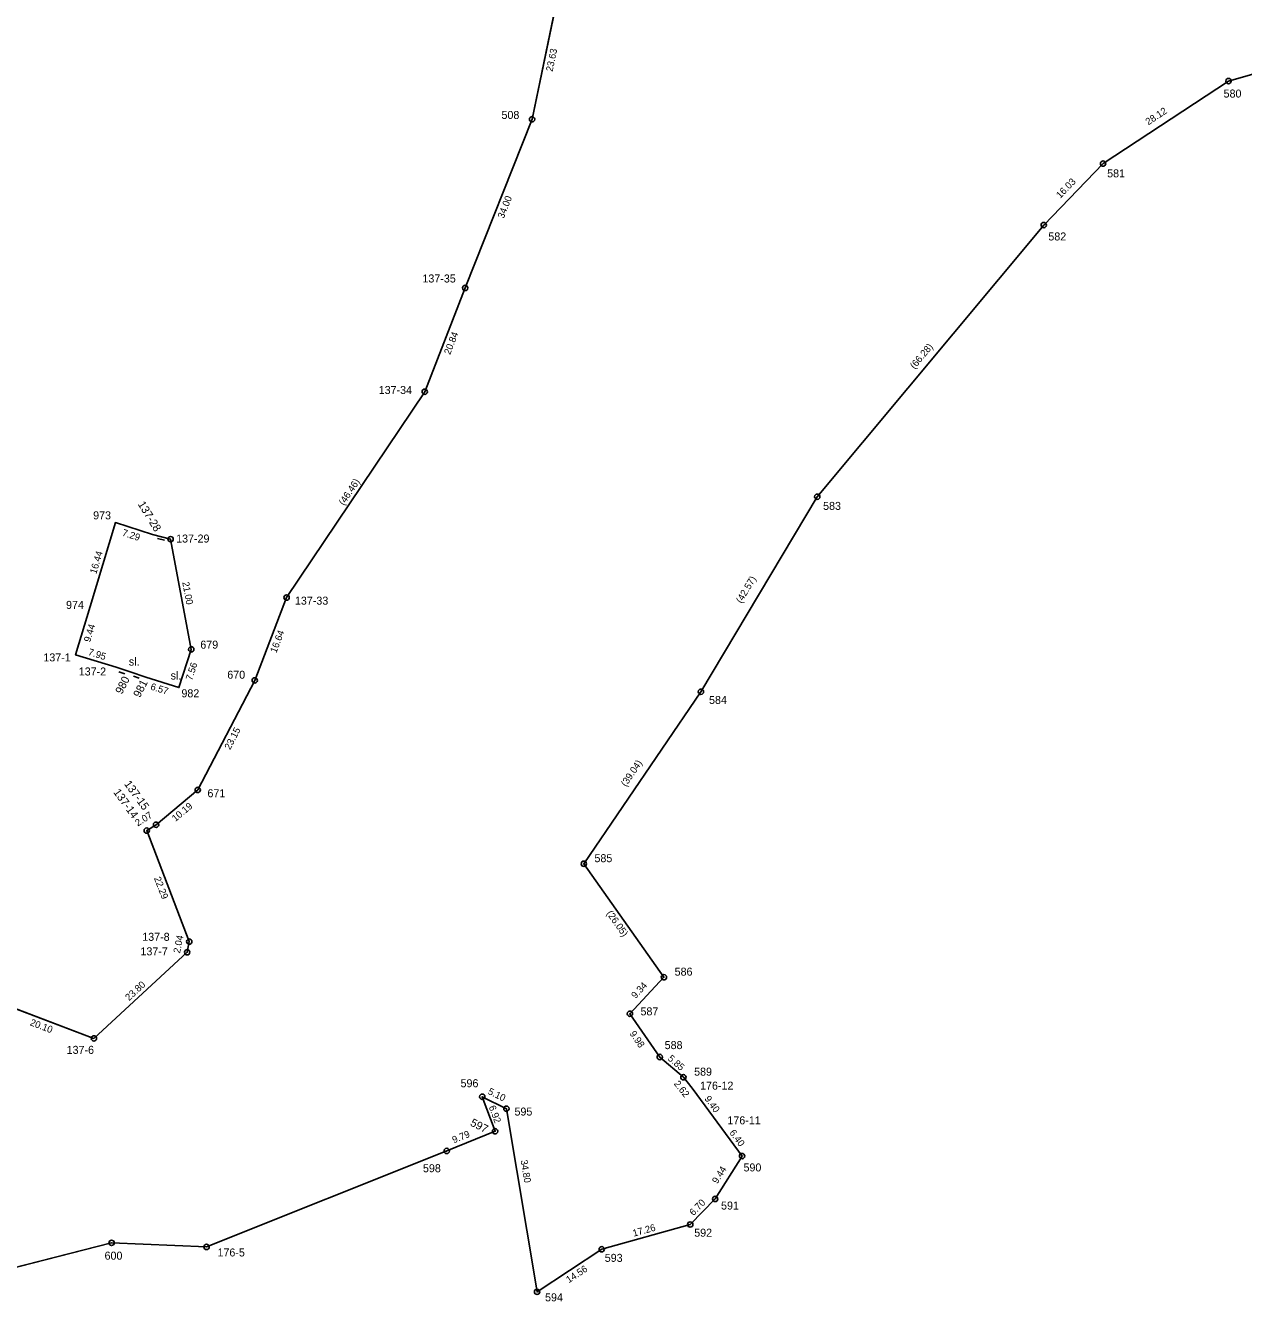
# Model space of a CAD drawing. Extents: x -555170 to -550532, y -1039598 to -1034701.
# Drawn here: x -554719.5 to -554491.3, y -1038084.3 to -1037842.9 of the extents above; entities that cross this region are included whole.
import ezdxf

# ---------------------------------------------------------------- set-up
doc = ezdxf.new("R2010")
doc.units = 0
for name, color, linetype in [('Vrstva 10', 7, 'Continuous'), ('Vrstva 40', 7, 'Continuous'), ('Vrstva 43', 7, 'Continuous'), ('Vrstva 48', 7, 'Continuous')]:
    doc.layers.add(name, color=color, linetype=linetype)

msp = doc.modelspace()

# ---------------------------------------------------------------- linework, layer by layer
at = {"layer": 'Vrstva 10'}
for p, q in [((-554693.54, -1037939.36), (-554694.82, -1037939.07)), ((-554701, -1037964.39), (-554702.12, -1037964.05)), ((-554698.29, -1037965.2), (-554699.35, -1037964.84))]:
    msp.add_line(p, q, dxfattribs=at)
at = {"layer": 'Vrstva 40'}
for p, q in [((-554619.81, -1037837.33), (-554624.63, -1037860.46)), ((-554494.07, -1037853.28), (-554482.94, -1037850.1)), ((-554517.59, -1037868.76), (-554494.07, -1037853.28)), ((-554624.63, -1037860.46), (-554637.17, -1037892.08)), ((-554528.71, -1037880.28), (-554517.59, -1037868.76)), ((-554571.15, -1037931.2), (-554528.71, -1037880.28)), ((-554637.17, -1037892.08), (-554644.76, -1037911.53)), ((-554644.76, -1037911.53), (-554670.64, -1037950.11)), ((-554592.96, -1037967.76), (-554571.15, -1037931.2)), ((-554702.73, -1037936.06), (-554707.46, -1037951.79)), ((-554695.8, -1037938.3), (-554702.73, -1037936.06)), ((-554692.38, -1037939.17), (-554695.8, -1037938.3)), ((-554688.52, -1037959.82), (-554692.38, -1037939.17)), ((-554670.64, -1037950.11), (-554676.61, -1037965.64)), ((-554707.46, -1037951.79), (-554710.2, -1037960.85)), ((-554710.2, -1037960.85), (-554702.61, -1037963.19)), ((-554690.82, -1037967), (-554688.52, -1037959.82)), ((-554702.61, -1037963.19), (-554699.98, -1037964.06)), ((-554699.98, -1037964.06), (-554697.06, -1037965.04)), ((-554697.06, -1037965.04), (-554690.82, -1037967)), ((-554676.61, -1037965.64), (-554687.3, -1037986.17)), ((-554614.93, -1038000.02), (-554592.96, -1037967.76)), ((-554687.3, -1037986.17), (-554695.12, -1037992.69)), ((-554695.12, -1037992.69), (-554696.87, -1037993.79)), ((-554696.87, -1037993.79), (-554688.89, -1038014.6)), ((-554599.9, -1038021.29), (-554614.93, -1038000.02)), ((-554689.29, -1038016.61), (-554706.76, -1038032.76)), ((-554688.89, -1038014.6), (-554689.29, -1038016.61)), ((-554606.27, -1038028.12), (-554599.9, -1038021.29)), ((-554706.76, -1038032.76), (-554725.56, -1038025.63)), ((-554600.69, -1038036.24), (-554606.27, -1038028.12)), ((-554596.25, -1038040.04), (-554600.69, -1038036.24)), ((-554594.63, -1038042.1), (-554596.25, -1038040.04)), ((-554589.08, -1038049.67), (-554594.63, -1038042.1)), ((-554631.56, -1038050.17), (-554633.97, -1038043.68)), ((-554633.97, -1038043.68), (-554629.43, -1038045.93)), ((-554629.43, -1038045.93), (-554623.69, -1038080.26)), ((-554640.63, -1038053.86), (-554631.56, -1038050.17)), ((-554585.27, -1038054.81), (-554589.08, -1038049.67)), ((-554685.65, -1038071.84), (-554640.63, -1038053.86)), ((-554590.31, -1038062.84), (-554585.27, -1038054.81)), ((-554594.98, -1038067.64), (-554590.31, -1038062.84)), ((-554611.56, -1038072.28), (-554594.98, -1038067.64)), ((-554754.97, -1038084.28), (-554703.45, -1038071.08)), ((-554703.45, -1038071.08), (-554685.65, -1038071.84)), ((-554623.69, -1038080.26), (-554611.56, -1038072.28))]:
    msp.add_line(p, q, dxfattribs=at)
at = {"layer": 'Vrstva 43'}
for p, q in [((-554494.07, -1037853.28), (-554494.07, -1037853.28)), ((-554624.63, -1037860.46), (-554624.63, -1037860.46)), ((-554517.59, -1037868.76), (-554517.59, -1037868.76)), ((-554528.71, -1037880.28), (-554528.71, -1037880.28)), ((-554637.17, -1037892.08), (-554637.17, -1037892.08)), ((-554644.76, -1037911.53), (-554644.76, -1037911.53)), ((-554571.15, -1037931.2), (-554571.15, -1037931.2)), ((-554702.73, -1037936.06), (-554702.73, -1037936.06)), ((-554695.8, -1037938.3), (-554695.8, -1037938.3)), ((-554692.38, -1037939.17), (-554692.38, -1037939.17)), ((-554670.64, -1037950.11), (-554670.64, -1037950.11)), ((-554707.46, -1037951.79), (-554707.46, -1037951.79)), ((-554710.2, -1037960.85), (-554710.2, -1037960.85)), ((-554688.52, -1037959.82), (-554688.52, -1037959.82)), ((-554702.61, -1037963.19), (-554702.61, -1037963.19)), ((-554699.98, -1037964.06), (-554699.98, -1037964.06)), ((-554697.06, -1037965.04), (-554697.06, -1037965.04)), ((-554676.61, -1037965.64), (-554676.61, -1037965.64)), ((-554690.82, -1037967), (-554690.82, -1037967)), ((-554592.96, -1037967.76), (-554592.96, -1037967.76)), ((-554687.3, -1037986.17), (-554687.3, -1037986.17)), ((-554696.87, -1037993.79), (-554696.87, -1037993.79)), ((-554695.12, -1037992.69), (-554695.12, -1037992.69)), ((-554614.93, -1038000.02), (-554614.93, -1038000.02)), ((-554689.29, -1038016.61), (-554689.29, -1038016.61)), ((-554688.89, -1038014.6), (-554688.89, -1038014.6)), ((-554599.9, -1038021.29), (-554599.9, -1038021.29)), ((-554606.27, -1038028.12), (-554606.27, -1038028.12)), ((-554706.76, -1038032.76), (-554706.76, -1038032.76)), ((-554600.69, -1038036.24), (-554600.69, -1038036.24)), ((-554596.25, -1038040.04), (-554596.25, -1038040.04)), ((-554594.63, -1038042.1), (-554594.63, -1038042.1)), ((-554633.97, -1038043.68), (-554633.97, -1038043.68)), ((-554629.43, -1038045.93), (-554629.43, -1038045.93)), ((-554631.56, -1038050.17), (-554631.56, -1038050.17)), ((-554589.08, -1038049.67), (-554589.08, -1038049.67)), ((-554640.63, -1038053.86), (-554640.63, -1038053.86)), ((-554585.27, -1038054.81), (-554585.27, -1038054.81)), ((-554590.31, -1038062.84), (-554590.31, -1038062.84)), ((-554594.98, -1038067.64), (-554594.98, -1038067.64)), ((-554703.45, -1038071.08), (-554703.45, -1038071.08)), ((-554685.65, -1038071.84), (-554685.65, -1038071.84)), ((-554611.56, -1038072.28), (-554611.56, -1038072.28)), ((-554623.69, -1038080.26), (-554623.69, -1038080.26))]:
    msp.add_line(p, q, dxfattribs=at)
for centre, radius in [((-554494.07, -1037853.28), 0.5), ((-554494.07, -1037853.28), 0.01), ((-554624.63, -1037860.46), 0.5), ((-554624.63, -1037860.46), 0.01), ((-554517.59, -1037868.76), 0.5), ((-554517.59, -1037868.76), 0.01), ((-554528.71, -1037880.28), 0.5), ((-554528.71, -1037880.28), 0.01), ((-554637.17, -1037892.08), 0.5), ((-554637.17, -1037892.08), 0.01), ((-554644.76, -1037911.53), 0.5), ((-554644.76, -1037911.53), 0.01), ((-554571.15, -1037931.2), 0.5), ((-554571.15, -1037931.2), 0.01), ((-554692.38, -1037939.17), 0.5), ((-554692.38, -1037939.17), 0.01), ((-554670.64, -1037950.11), 0.5), ((-554670.64, -1037950.11), 0.01), ((-554688.52, -1037959.82), 0.5), ((-554688.52, -1037959.82), 0.01), ((-554676.61, -1037965.64), 0.5), ((-554676.61, -1037965.64), 0.01), ((-554592.96, -1037967.76), 0.5), ((-554592.96, -1037967.76), 0.01), ((-554687.3, -1037986.17), 0.5), ((-554687.3, -1037986.17), 0.01), ((-554695.12, -1037992.69), 0.5), ((-554696.87, -1037993.79), 0.5), ((-554696.87, -1037993.79), 0.01), ((-554695.12, -1037992.69), 0.01), ((-554614.93, -1038000.02), 0.5), ((-554614.93, -1038000.02), 0.01), ((-554688.89, -1038014.6), 0.5), ((-554689.29, -1038016.61), 0.5), ((-554689.29, -1038016.61), 0.01), ((-554688.89, -1038014.6), 0.01), ((-554599.9, -1038021.29), 0.5), ((-554599.9, -1038021.29), 0.01), ((-554606.27, -1038028.12), 0.5), ((-554606.27, -1038028.12), 0.01), ((-554706.76, -1038032.76), 0.5), ((-554706.76, -1038032.76), 0.01), ((-554600.69, -1038036.24), 0.5), ((-554600.69, -1038036.24), 0.01), ((-554596.25, -1038040.04), 0.5), ((-554596.25, -1038040.04), 0.01), ((-554633.97, -1038043.68), 0.5), ((-554633.97, -1038043.68), 0.01), ((-554629.43, -1038045.93), 0.5), ((-554629.43, -1038045.93), 0.01), ((-554631.56, -1038050.17), 0.5), ((-554631.56, -1038050.17), 0.01), ((-554640.63, -1038053.86), 0.5), ((-554640.63, -1038053.86), 0.01), ((-554585.27, -1038054.81), 0.5), ((-554585.27, -1038054.81), 0.01), ((-554590.31, -1038062.84), 0.5), ((-554590.31, -1038062.84), 0.01), ((-554594.98, -1038067.64), 0.5), ((-554594.98, -1038067.64), 0.01), ((-554703.45, -1038071.08), 0.5), ((-554703.45, -1038071.08), 0.01), ((-554685.65, -1038071.84), 0.5), ((-554685.65, -1038071.84), 0.01), ((-554611.56, -1038072.28), 0.5), ((-554611.56, -1038072.28), 0.01), ((-554623.69, -1038080.26), 0.5), ((-554623.69, -1038080.26), 0.01)]:
    msp.add_circle(centre, radius, dxfattribs=at)
at = {"layer": 'Vrstva 48'}
for points in [[(-554725.56, -1038025.63), (-554706.76, -1038032.76), (-554689.29, -1038016.61), (-554688.89, -1038014.6), (-554696.87, -1037993.79), (-554695.12, -1037992.69), (-554687.3, -1037986.17), (-554676.61, -1037965.64), (-554670.64, -1037950.11), (-554644.76, -1037911.53), (-554637.17, -1037892.08), (-554624.63, -1037860.46), (-554619.81, -1037837.33)], [(-554482.94, -1037850.1), (-554494.07, -1037853.28), (-554517.59, -1037868.76), (-554528.71, -1037880.28), (-554571.15, -1037931.2), (-554592.96, -1037967.76), (-554614.93, -1038000.02), (-554599.9, -1038021.29), (-554606.27, -1038028.12), (-554600.69, -1038036.24), (-554596.25, -1038040.04), (-554594.63, -1038042.1), (-554589.08, -1038049.67), (-554585.27, -1038054.81), (-554590.31, -1038062.84), (-554594.98, -1038067.64), (-554611.56, -1038072.28), (-554623.69, -1038080.26), (-554629.43, -1038045.93), (-554633.97, -1038043.68), (-554631.56, -1038050.17), (-554640.63, -1038053.86), (-554685.65, -1038071.84), (-554703.45, -1038071.08), (-554754.97, -1038084.28)], [(-554702.61, -1037963.19), (-554710.2, -1037960.85), (-554707.46, -1037951.79), (-554702.73, -1037936.06), (-554695.8, -1037938.3), (-554692.38, -1037939.17), (-554688.52, -1037959.82), (-554690.82, -1037967), (-554697.06, -1037965.04), (-554699.98, -1037964.06), (-554702.61, -1037963.19)]]:
    msp.add_lwpolyline(points, dxfattribs=at)

# ---------------------------------------------------------------- texts
at = {"layer": 'Vrstva 10'}
for s, rotation, p in [('23.63', 78.2168, (-554620.79, -1037851.6)), ('28.12', 33.3514, (-554509.1, -1037861.6)), ('16.03', 46.0122, (-554525.61, -1037875.38)), ('34.00', 68.3742, (-554629.95, -1037879.16)), ('20.84', 68.6827, (-554639.99, -1037904.67)), ('(66.28)', 50.1933, (-554552.91, -1037907.37)), ('(46.46)', 56.1457, (-554659.91, -1037932.94)), ('7.29', 342.0875, (-554701.58, -1037938.48)), ('16.44', 73.264, (-554706.33, -1037945.79)), ('(42.57)', 59.1798, (-554585.37, -1037951.3)), ('21.00', 280.5922, (-554690.21, -1037947.26)), ('9.44', 73.1732, (-554707.47, -1037958.56)), ('16.64', 68.9713, (-554672.58, -1037960.6)), ('7.95', 342.8655, (-554707.96, -1037960.86)), ('7.56', 72.2436, (-554688.37, -1037965.75)), ('6.57', 342.5624, (-554696.27, -1037967.33)), ('23.15', 62.4958, (-554681.23, -1037978.74)), ('(39.04)', 55.7362, (-554607.01, -1037985.66)), ('10.19', 39.8168, (-554691.49, -1037992.2)), ('2.07', 32.1523, (-554698.54, -1037993.05)), ('22.29', 290.9803, (-554695.53, -1038002.72)), ('(26.05)', 305.2609, (-554610.75, -1038009.32)), ('2.04', 78.7449, (-554690.63, -1038016.87)), ('23.80', 42.7516, (-554700.18, -1038025.79)), ('9.34', 46.9658, (-554605.24, -1038025.4)), ('20.10', 339.2385, (-554718.86, -1038030.26)), ('9.98', 304.5258, (-554606.4, -1038031.87)), ('5.85', 319.3987, (-554599.3, -1038036.7)), ('2.62', 308.2456, (-554598.12, -1038041.28)), ('5.10', 333.6372, (-554633.03, -1038043.12)), ('6.92', 290.3332, (-554632.77, -1038045.59)), ('9.40', 306.2473, (-554592.37, -1038044.08)), ('9.79', 22.1537, (-554639.29, -1038052.44)), ('6.40', 306.5435, (-554587.7, -1038050.44)), ('34.80', 279.4923, (-554626.79, -1038055.62)), ('9.44', 57.8881, (-554589.9, -1038060.11)), ('6.70', 45.7865, (-554594.37, -1038066.08)), ('17.26', 15.6346, (-554605.56, -1038069.93)), ('14.56', 33.3224, (-554617.73, -1038078.67))]:
    msp.add_text(s, height=1.3, rotation=rotation, dxfattribs=at).set_placement(p)
at = {"layer": 'Vrstva 43'}
for s, p in [('580', (-554494.99, -1037856.38)), ('508', (-554630.36, -1037860.39)), ('581', (-554516.82, -1037871.34)), ('582', (-554527.84, -1037883.17)), ('137-35', (-554645.18, -1037891.05)), ('137-34', (-554653.38, -1037911.95)), ('583', (-554570.07, -1037933.68)), ('973', (-554706.91, -1037935.45)), ('137-29', (-554691.35, -1037939.8)), ('974', (-554711.99, -1037952.24)), ('137-33', (-554669.08, -1037951.44)), ('679', (-554686.82, -1037959.69)), ('137-1', (-554716.24, -1037962.08)), ('137-2', (-554709.61, -1037964.72)), ('sl.', (-554700.22, -1037962.86)), ('sl.', (-554692.39, -1037965.48)), ('670', (-554681.76, -1037965.33)), ('982', (-554690.36, -1037968.81)), ('584', (-554591.45, -1037970.06)), ('671', (-554685.48, -1037987.55)), ('585', (-554612.93, -1037999.72)), ('137-8', (-554697.7, -1038014.46)), ('137-7', (-554698.04, -1038017.18)), ('586', (-554597.9, -1038020.99)), ('587', (-554604.3, -1038028.44)), ('588', (-554599.77, -1038034.76)), ('137-6', (-554711.88, -1038035.65)), ('589', (-554594.25, -1038039.74)), ('596', (-554638.03, -1038041.91)), ('176-12', (-554593.13, -1038042.36)), ('595', (-554627.92, -1038047.22)), ('176-11', (-554588.01, -1038048.86)), ('598', (-554645.08, -1038057.84)), ('590', (-554584.99, -1038057.69)), ('591', (-554589.2, -1038064.84)), ('592', (-554594.23, -1038069.93)), ('176-5', (-554683.6, -1038073.63)), ('600', (-554704.77, -1038074.23)), ('593', (-554611, -1038074.64)), ('594', (-554622.19, -1038082.04))]:
    msp.add_text(s, height=1.5, dxfattribs=at).set_placement(p)
for s, rotation, p in [('137-28', 301.5, (-554698.59, -1037932.6)), ('980', 63, (-554701.52, -1037968.34)), ('981', 63, (-554698.15, -1037968.98)), ('137-15', 306, (-554701.17, -1037985.07)), ('137-14', 306, (-554703.2, -1037986.62)), ('597', 333, (-554636.34, -1038049.02))]:
    msp.add_text(s, height=1.5, rotation=rotation, dxfattribs=at).set_placement(p)

doc.saveas('drawing.dxf')
